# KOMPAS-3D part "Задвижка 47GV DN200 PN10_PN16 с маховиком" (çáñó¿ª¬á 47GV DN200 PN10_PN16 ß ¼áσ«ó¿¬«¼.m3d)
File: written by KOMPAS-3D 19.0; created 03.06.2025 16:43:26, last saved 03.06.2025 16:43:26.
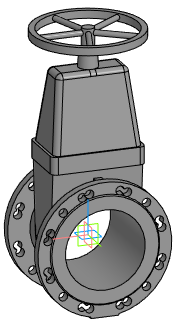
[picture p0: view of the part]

Document properties: Автор: Евгений; Полное имя файла: E:\Dendor Работа Сачек\3D для проекитирвщиков\2.1 Тип 47GV, 47GV.Z Задвижка клиновая фланцевая с обрезиненным клином\stp_Тип 47GV. Задвижка DN40-DN350 с маховиком\Задвижка 47GV DN200 PN10_PN16 с маховиком.m3d

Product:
- Part/product: Задвижка 47GV DN200 PN10_PN16 с маховиком

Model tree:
1. Операция без истории:1  (labels: Задвижка 47GV DN200 PN10_PN16 с маховиком)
